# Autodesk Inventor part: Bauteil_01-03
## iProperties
Created: 2007-04
Part Number: Bauteil_01-03
Document SubType Name: Modeling
Designer: Sascha Fleischer
Author: Sascha Fleischer
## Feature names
1. Abgeleiteter Körper1 [Tagging]
